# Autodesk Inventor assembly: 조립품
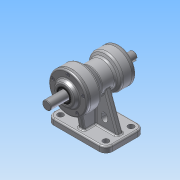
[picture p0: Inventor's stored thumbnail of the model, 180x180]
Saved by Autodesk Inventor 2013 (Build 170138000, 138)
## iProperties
Created: 2015-08
Part Number: 조립품
Document SubType Name: Assembly
Designer: Administrator
Author: Administrator
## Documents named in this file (10)
- C:\Users\Administrator\Desktop\450806V1014\조립품.iam
- C:\Users\Administrator\Desktop\450806V1014\01 본체.ipt
- C:\Users\Administrator\Desktop\450806V1014\M4x0.5.ipt
- C:\Users\Administrator\Desktop\450806V1014\뒤커버.ipt
- C:\Users\Administrator\Desktop\450806V1014\베어링 6203.ipt
- C:\Users\Administrator\Desktop\450806V1014\베어링 6205.ipt
- C:\Users\Administrator\Desktop\450806V1014\앞커버.ipt
- C:\Users\Administrator\Desktop\450806V1014\오일실 .ipt
- 오일실 .ipt
- C:\Users\Administrator\Desktop\450806V1014\축.ipt
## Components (11 placed, 2 different names)
1. 01 본체:1
2. M4x0.5:2
3. M4x0.5:3
4. M4x0.5:4
5. M4x0.5:5
6. M4x0.5:6
7. M4x0.5:1
8. M4x0.5:7
9. M4x0.5:8
10. M4x0.5:9
11. M4x0.5:10
